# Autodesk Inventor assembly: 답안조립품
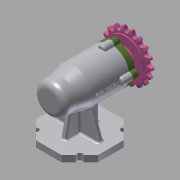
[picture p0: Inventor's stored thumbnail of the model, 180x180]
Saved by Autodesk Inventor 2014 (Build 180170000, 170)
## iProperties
Created: 2021-01
Part Number: 답안조립품
Document SubType Name: Assembly
Designer: kh
Author: kh
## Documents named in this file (12)
- C:\Users\kh\Desktop\710106V1012\답안조립품.iam
- C:\Users\kh\Desktop\710106V1012\본체.ipt
- C:\Users\kh\Desktop\710106V1012\멈춤나사 M3.ipt
- C:\Users\kh\Desktop\710106V1012\베어링 6004.ipt
- C:\Users\kh\Desktop\710106V1012\베어링 51202.ipt
- C:\Users\kh\Desktop\710106V1012\볼트 M4.ipt
- C:\Users\kh\Desktop\710106V1012\스프로킷.ipt
- C:\Users\kh\Desktop\710106V1012\어댑터슬리브.ipt
- C:\Users\kh\Desktop\710106V1012\오일 실.ipt
- C:\Users\kh\Desktop\710106V1012\축.ipt
- C:\Users\kh\Desktop\710106V1012\커버.ipt
- C:\Users\kh\Desktop\710106V1012\키 5 x 5 x 14.ipt
